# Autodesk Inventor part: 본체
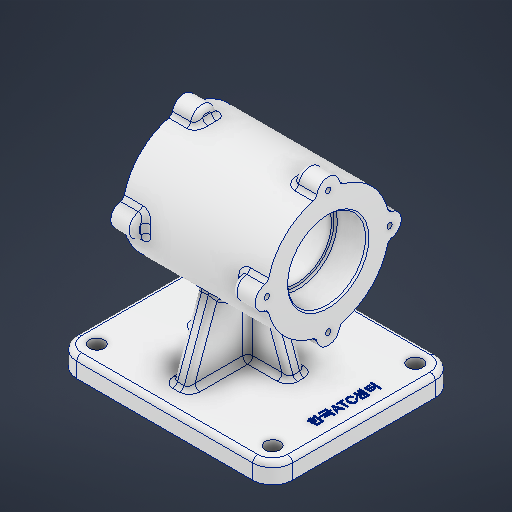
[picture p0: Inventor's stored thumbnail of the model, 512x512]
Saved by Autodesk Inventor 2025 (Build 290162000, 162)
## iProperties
Created: 2025-08
Part Number: 본체
Material: 알루미늄 6061
Document SubType Name: Modeling
Designer: infra10
Density: 2.7 g/cm^3
Appearance: 알루미늄 - 평지
Author: infra10
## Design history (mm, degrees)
sketch "스케치2"
  geometry: L1 (65, -55)-(-65, -55); L2 (-65, -55)-(-65, 55); L3 (-65, 55)-(65, 55); L4 (65, 55)-(65, -55); L5 (65, -55)-(-65, 55); L6 (-65, -55)-(65, 55); 1 further point
  constraints: 12 end point, 2 midpoint, 2 parallel, 1 horizontal, 1 perpendicular
  dimensions: "d0" = 130 distance of L2.end L3.end; "d1" = 110 distance of L1.end L2.end
extrude "돌출1" new body sketch "스케치2" stored distance "d2" = 12; taper "d3" = 0 deg
sketch "스케치4"
  geometry: L1 (-6, -55)-(-6, 55) reference; C1 r 37 at (76, 0); 2 further points
  constraints: 1 centre point, 1 midpoint
  dimensions: "d4" = 74 diameter of C1; "d49" = 82 distance of point (-6, 0) C1.centre
extrude "돌출2" join sketch "스케치4" stored distance "d5" = 87; taper "d6" = 0 deg
sketch "스케치5"
  geometry: C1 r 7 at (0, 37); C2 r 7 at (-37, 0); C3 r 7 at (0, -37); C4 r 7 at (37, 0); 2 further points
  constraints: 4 centre point, 1 vertical alignment, 10 other
  dimensions: "d7" = 14 diameter of C1; "d10" = 360 deg dimension on point (0, 0) C1.centre (derived)
extrude "돌출3" join sketch "스케치5" distance "d12" = 14; taper "d13" = 0 deg
sketch "스케치6"
  geometry: A1 r 7 centre (0, 113) between (6.969, 112.338) and (-6.969, 112.338) reference; 6 further points
  constraints: 1 coincident, 5 other
  dimensions: "d21" = 37 distance of point (0, 76) point (0, 113); "d24" = 360 deg dimension on point (0, 76) point (0, 113) (derived)
  node "스케치 - 원형 패턴2" dims "d24" = 360 deg (derived)
hole "구멍1" sketch "스케치6" diameter "d14" = 42; stored, may be unused: countersink angle "d18" = 90 deg, drill point angle "d20" = 0 deg; dims "d15" = 8, "d16" = 47, "d17" = 19, "d19" = 10
hole "구멍2" sketch "스케치6" diameter "d26" = 3.242; stored, may be unused: countersink angle "d30" = 90 deg, drill point angle "d32" = 118 deg; dims "d27" = 8, "d28" = 47, "d29" = 19, "d31" = 10
fillet "모깎기1" dims "d33" = 3
fillet "모깎기2" dims "d34" = 1
chamfer "모따기1" distance "d35" = 1; stored, may be unused: second distance "d36" = 2, angle "d37" = 45 deg
sketch "스케치7"
  geometry: C1 r 21 at (0, 76) reference; 2 further points
  constraints: 1 coincident
hole "구멍3" sketch "스케치7" at (0, 76) diameter "d38" = 42; stored, may be unused: countersink angle "d42" = 90 deg, drill point angle "d44" = 118 deg; dims "d39" = 8, "d40" = 47, "d41" = 19, "d43" = 10
fillet "모깎기3" dims "d45" = 1
chamfer "모따기2" distance "d46" = 1; stored, may be unused: second distance "d47" = 2, angle "d48" = 45 deg
sketch "스케치13"
  geometry: L1 (53, -43)-(-53, -43); L2 (-53, -43)-(-53, 43); L3 (-53, 43)-(53, 43); L4 (53, 43)-(53, -43); L5 (53, -43)-(-53, 43); L6 (-53, -43)-(53, 43); 1 further point
  constraints: 12 end point, 2 midpoint, 2 parallel, 1 horizontal, 1 perpendicular
  dimensions: "d76" = 86 distance between parallel lines of L1 L3; "d77" = 106 distance between parallel lines of L4 L2
hole "구멍4" sketch "스케치13" at (-53, -43), (-53, 43), (53, 43), (53, -43) diameter "d78" = 9; stored, may be unused: countersink angle "d82" = 90 deg, drill point angle "d84" = 118 deg; dims "d79" = 6, "d80" = 47, "d81" = 19, "d83" = 8
fillet "모깎기4" dims "d85" = 12
fillet "모깎기6" dims "d88" = 3
node "작업 평면2"
sketch "스케치16"
  geometry: L1 (6, -38.5)-(6, -47.5) reference; L2 (49.036, -25.336)-(6, -41); L3 (-6, -55)-(3, -55) reference; L4 (39, 0)-(6, 0); L5 (6, 43)-(6, -43) reference; C1 r 1.621 at (39, 0) reference; A1 r 37 centre (76, 0) between (40.138, -9.104) and (66.896, -35.862) reference; 1 further point
  constraints: 4 end point, 1 midpoint, 1 point on circle, 1 point on line
  dimensions: "d110" = 14 distance from line of L2.end L3; "d111" = 110 deg angle of L1 L2
feature "리브5" sketch "스케치16" dims "d112" = 1, "d113" = 10, "d114" = 0, "d115" = 0, "d116" = 1, "d117" = 1
sketch "스케치18"
  geometry: L1 (-26.5, 39)-(26.5, 39) reference; L2 (53, 6)-(-53, 6) reference; L3 (12.989, 39)-(25, 6); L4 (0, 49.036)-(-10, 49.036) reference; 2 further points
  constraints: 2 end point, 2 point on line, 1 midpoint
  dimensions: "d118" = 30 horizontal distance of L3.end point (-5, 49.036); "d119" = 110 deg angle of L2 L3
feature "리브6" sketch "스케치18" dims "d120" = 1, "d121" = 10, "d122" = 0, "d123" = 0, "d124" = 1, "d125" = 1
node "작업 평면4"
sketch "스케치12" dims "d0" = 130, "d1" = 110
  geometry: L1 (27.509, -3.593)-(27.509, 3.593); L2 (27.509, 3.593)-(78.491, 3.593); L3 (78.491, 3.593)-(78.491, -3.593); L4 (78.491, -3.593)-(27.509, -3.593); L5 (65, 55)-(-65, 55) reference; L6 (65, -55)-(65, 55) reference; L7 (-10, 41)-(0, 41) reference; 6 further points
  constraints: 5 midpoint, 2 other
  dimensions: "d72" = 7.18601 distance between parallel lines of L4 L2; "d73" = 3.593 distance from line of L4 point (65, 0) (= 0.5 x d72); "d126" = 58 horizontal distance of point (-5, 41) point (53, -3.593)
feature "엠보싱1" sketch "스케치12" dims "d0" = 130, "d1" = 110, "d74" = 0.5, "d75" = 0
fillet "모깎기11" dims "d127" = 3
fillet "모깎기12" dims "d128" = 2
node "솔리드1"
mirror "미러1"
mirror "미러5"
mirror "미러6"
node "스케치 - 원형 패턴1" dims "d10" = 360 deg (derived)
node "작업 평면3"
feature "A9D066F2-1C7D-4E18-AEED-F7BC21143FA4" dims "d14" = 42, "d15" = 8, "d16" = 47, "d17" = 19, "d18" = 90 deg, "d19" = 10, "d20" = 0
other parameters: "d109" = -5
